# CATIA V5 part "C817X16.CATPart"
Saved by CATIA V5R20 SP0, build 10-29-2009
Part number: C817X16
Source: Unknown
Property "A": "56.5"
Property "ARTICLENO": "C817XC16"
Property "B": "13"
Property "BOMINFO": "C817XC16"
Property "C": "14.5"
Property "CA": "C817XC16"
Property "D": "39"
Property "DES": "EYEBOLT TWISTER WITH BEARING M16 WITH KEY"
Property "E": "56"
Property "F": "33.0"
Property "K": "65"
Property "L": "24.0"
Property "LINA": "C817XC16"
Property "NB": "C817XC16"
Property "NBSYN": "$CODE."
Property "NN": "C817X"
Property "NT": "Eyebolt twister with bearing"
Property "SIZE": "M16"
Property "SUPPLIER": "CF"
Property "WEIGHT": "900"
Property "WLL": "1.50"
Bounding box of the stored display mesh (mm): x -32.465 to 32.465, y -24 to 69.5, z -29.802 to 29.802
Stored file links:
  C:\Users\Utente\Desktop\3D files 817X\C817X16.CATPart
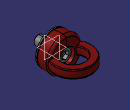
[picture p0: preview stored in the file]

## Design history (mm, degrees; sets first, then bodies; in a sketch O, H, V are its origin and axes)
Body1 "Geometry.1" (main body)
  Solid1 "C817XC16.catpart": solid without history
